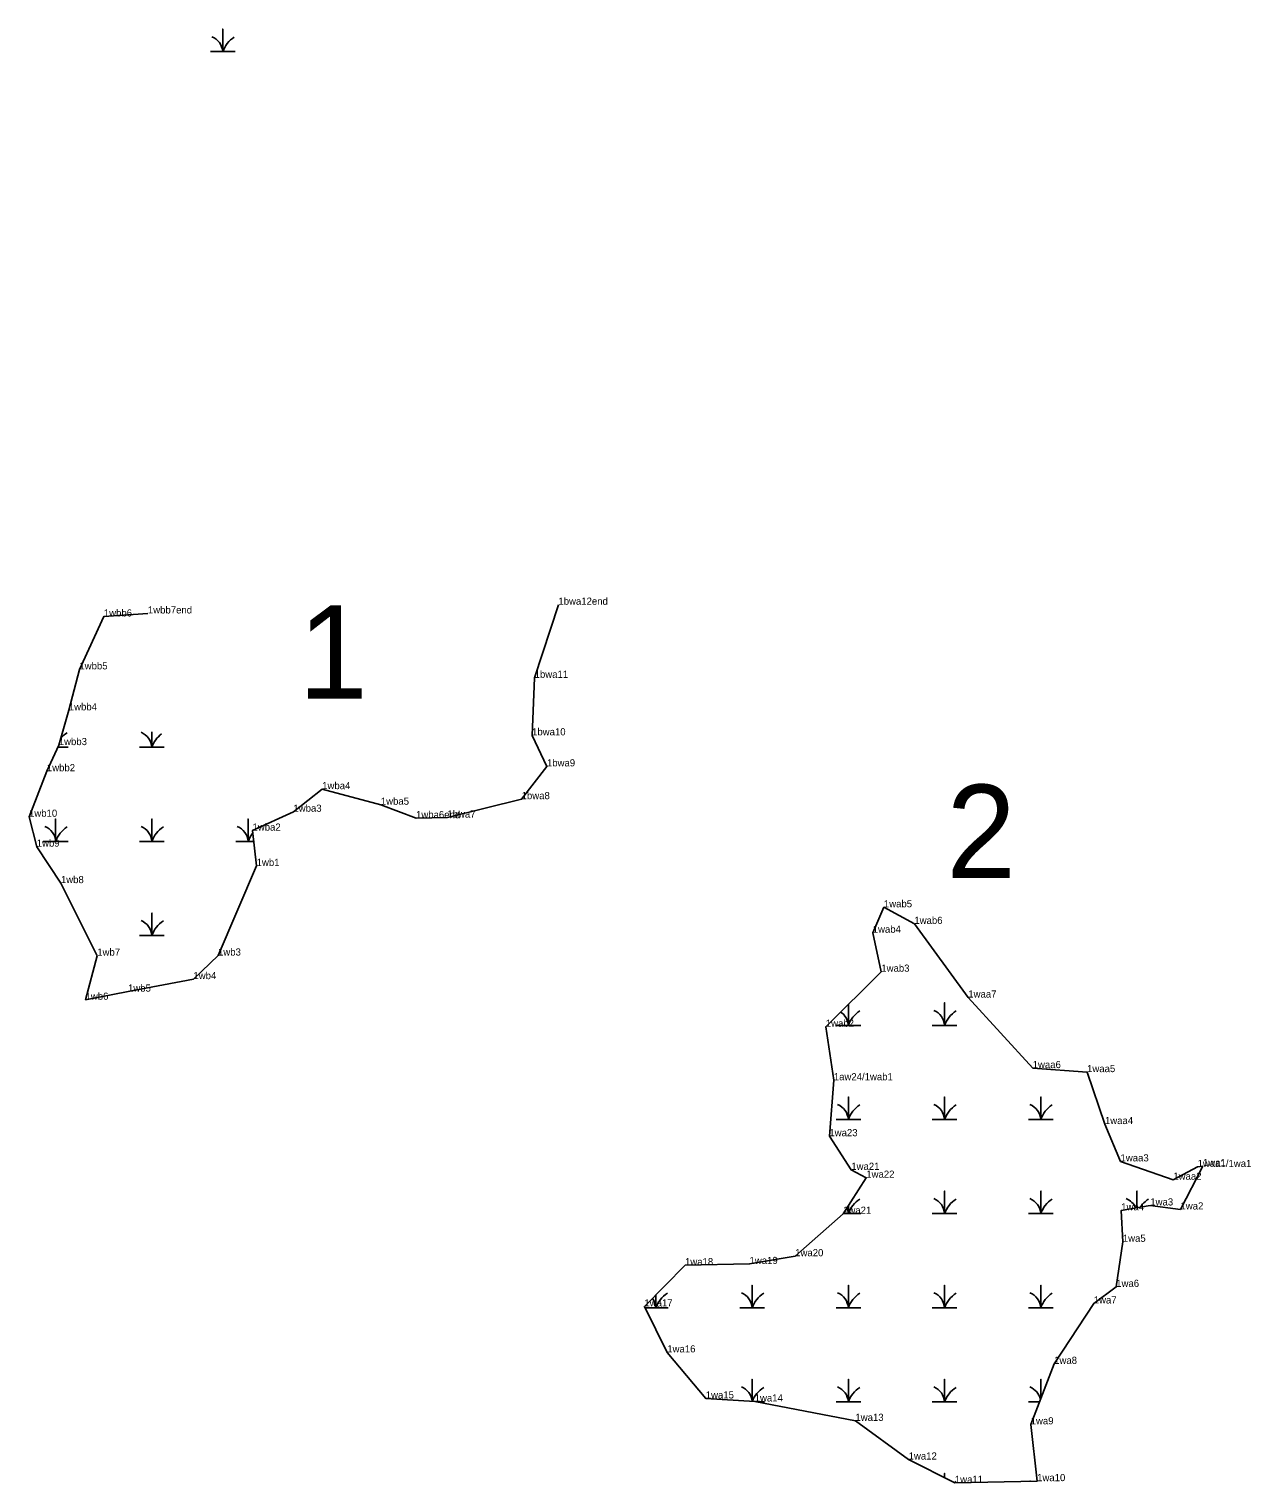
# Model space of a CAD drawing. Extents: x 2072529 to 2268796, y 436423 to 470406.
# Drawn here: x 2072529 to 2073383, y 469389 to 470406 of the extents above; entities that cross this region are included whole.
import ezdxf

# ---------------------------------------------------------------- set-up
doc = ezdxf.new("R2010")
doc.units = 0
for name, color, linetype in [('Default', 7, 'Continuous'), ('Exist Environmental Wetland Boundary', 7, 'Continuous'), ('Exist Environmental Wetland Boundary Cogo Comment', 7, 'Continuous'), ('Exist Hydro Swamp or Marsh', 7, 'Continuous'), ('Old_Level_20', 7, 'Continuous')]:
    doc.layers.add(name, color=color, linetype=linetype)

msp = doc.modelspace()

# ---------------------------------------------------------------- linework, layer by layer
at = {"layer": 'Exist Environmental Wetland Boundary'}
msp.add_line((2073333.7, 469580.5), (2073349.4, 469610.8), dxfattribs=at)
for points in [[(2072612, 469997.1), (2072581.2, 469995), (2072564.1, 469958), (2072556.7, 469929.4), (2072549.7, 469905.1), (2072541.4, 469886.8), (2072528.9, 469855)], [(2072898.9, 470003.2), (2072882.3, 469952.1), (2072880.5, 469911.9), (2072890.9, 469890.2), (2072873.2, 469867.3), (2072821.3, 469854.4), (2072799.4, 469854)], [(2072799.4, 469854), (2072774.8, 469863.4), (2072733.8, 469874.3), (2072713.7, 469858.5), (2072685.1, 469845.3), (2072688, 469820.6)], [(2072528.9, 469855), (2072534.3, 469834.1), (2072551.2, 469808.6), (2072576.6, 469757.9), (2072568.4, 469727.1), (2072598.1, 469732.8), (2072643.8, 469741.5), (2072661, 469758), (2072688, 469820.6)], [(2073091.4, 469670.8), (2073085.8, 469708.2), (2073124.6, 469746.7), (2073118.6, 469773.9), (2073126.4, 469791.7), (2073147.7, 469780.1), (2073185.4, 469728.6), (2073230.4, 469679.3), (2073268.4, 469676.5), (2073280.9, 469640.2), (2073291.8, 469614.1), (2073328.7, 469601.3), (2073345.7, 469610.2), (2073349.4, 469610.8)], [(2073091.4, 469670.8), (2073088.3, 469631.7), (2073103.6, 469608.2), (2073114.1, 469602.7), (2073097.9, 469577.5), (2073064.4, 469547.8), (2073032.5, 469542.4), (2072987.4, 469541.5), (2072959, 469512.7), (2072975, 469480.6), (2073001.9, 469448.4), (2073036.1, 469446.3), (2073106.5, 469432.7), (2073143.7, 469405.7), (2073176, 469389.4), (2073233.5, 469390.6), (2073229, 469430.3), (2073245.4, 469472.6), (2073273.1, 469514.8), (2073288.8, 469526.4), (2073293.4, 469557.9), (2073292.3, 469579.9), (2073312.6, 469583.3), (2073333.7, 469580.5)]]:
    msp.add_lwpolyline(points, dxfattribs=at)
at = {"layer": 'Exist Hydro Swamp or Marsh'}
msp.add_line((2072664.3, 470396.9), (2072664.3, 470396.9), dxfattribs=at)
for points in [[(2072655.7, 470389.8), (2072664.3, 470389.8), (2072664.3, 470405.6), (2072664.3, 470389.8), (2072672.9, 470389.8)], [(2072606.2, 469903.6), (2072614.8, 469903.6), (2072614.8, 469914.4)], [(2072614.8, 469914.4), (2072614.8, 469903.6), (2072623.4, 469903.6)], [(2072549, 469903.6), (2072556.2, 469903.6)], [(2072538.9, 469837.8), (2072547.5, 469837.8), (2072547.5, 469853.5), (2072547.5, 469837.8), (2072556.2, 469837.8)], [(2072606.2, 469837.8), (2072614.8, 469837.8), (2072614.8, 469853.5), (2072614.8, 469837.8), (2072623.4, 469837.8)], [(2072673.4, 469837.8), (2072682, 469837.8), (2072682, 469853.5), (2072682, 469837.8), (2072686, 469837.8)], [(2072606.2, 469772), (2072614.8, 469772), (2072614.8, 469787.7), (2072614.8, 469772), (2072623.4, 469772)], [(2073093, 469709.2), (2073101.6, 469709.2), (2073101.6, 469723.9)], [(2073101.6, 469723.9), (2073101.6, 469709.2), (2073110.2, 469709.2)], [(2073160.2, 469709.2), (2073168.8, 469709.2), (2073168.8, 469725), (2073168.8, 469709.2), (2073177.4, 469709.2)], [(2073093, 469643.4), (2073101.6, 469643.4), (2073101.6, 469659.2), (2073101.6, 469643.4), (2073110.2, 469643.4)], [(2073160.2, 469643.4), (2073168.8, 469643.4), (2073168.8, 469659.2), (2073168.8, 469643.4), (2073177.4, 469643.4)], [(2073227.5, 469643.4), (2073236.1, 469643.4), (2073236.1, 469659.2), (2073236.1, 469643.4), (2073244.7, 469643.4)], [(2073160.2, 469577.6), (2073168.8, 469577.6), (2073168.8, 469593.4), (2073168.8, 469577.6), (2073177.4, 469577.6)], [(2073227.5, 469577.6), (2073236.1, 469577.6), (2073236.1, 469593.4), (2073236.1, 469577.6), (2073244.7, 469577.6)], [(2073303.3, 469581.7), (2073303.3, 469593.4), (2073303.3, 469581.7)], [(2073098, 469577.6), (2073101.6, 469577.6), (2073101.6, 469583.2)], [(2073101.6, 469583.2), (2073101.6, 469577.6), (2073110.2, 469577.6)], [(2072959.5, 469511.8), (2072967.1, 469511.8), (2072967.1, 469520.9)], [(2072967.1, 469520.9), (2072967.1, 469511.8), (2072975.7, 469511.8)], [(2073025.7, 469511.8), (2073034.3, 469511.8), (2073034.3, 469527.6), (2073034.3, 469511.8), (2073042.9, 469511.8)], [(2073093, 469511.8), (2073101.6, 469511.8), (2073101.6, 469527.6), (2073101.6, 469511.8), (2073110.2, 469511.8)], [(2073160.2, 469511.8), (2073168.8, 469511.8), (2073168.8, 469527.6), (2073168.8, 469511.8), (2073177.4, 469511.8)], [(2073227.5, 469511.8), (2073236.1, 469511.8), (2073236.1, 469527.6), (2073236.1, 469511.8), (2073244.7, 469511.8)], [(2073034.3, 469446.4), (2073034.3, 469461.8), (2073034.3, 469446.4)], [(2073093, 469446), (2073101.6, 469446), (2073101.6, 469461.8), (2073101.6, 469446), (2073110.2, 469446)], [(2073160.2, 469446), (2073168.8, 469446), (2073168.8, 469461.8), (2073168.8, 469446), (2073177.4, 469446)], [(2073236.1, 469448.5), (2073236.1, 469461.8), (2073236.1, 469448.5)], [(2073037.7, 469446), (2073042.9, 469446)], [(2073227.5, 469446), (2073235.1, 469446)], [(2073168.8, 469393), (2073168.8, 469396), (2073168.8, 469393)]]:
    msp.add_lwpolyline(points, dxfattribs=at)
for centre, radius, start, end in [((2072652, 470388.9), 12.3, 4.1403, 67.535), ((2072682.6, 470383.7), 19.2, 122.1274, 161.6222), ((2072565.8, 469897.5), 19.2, 122.1274, 139.9617), ((2072602.5, 469902.7), 12.3, 4.1403, 67.535), ((2072633, 469897.5), 19.2, 126.6727, 161.6222), ((2072535.3, 469836.9), 12.3, 4.1403, 67.535), ((2072565.8, 469831.7), 19.2, 122.1274, 161.6222), ((2072602.5, 469836.9), 12.3, 4.1403, 67.535), ((2072633, 469831.7), 19.2, 122.1274, 161.6222), ((2072669.8, 469836.9), 12.3, 4.1403, 67.535), ((2072700.3, 469831.7), 19.2, 122.1274, 127.5328), ((2072700.3, 469831.7), 19.2, 141.3706, 161.6222), ((2072602.5, 469771.1), 12.3, 4.1403, 67.535), ((2072633, 469765.9), 19.2, 122.1274, 161.6222), ((2073089.3, 469708.3), 12.3, 4.1403, 56.041), ((2073119.8, 469703.1), 19.2, 122.1274, 161.6222), ((2073156.6, 469708.3), 12.3, 4.1403, 67.535), ((2073187.1, 469703.1), 19.2, 122.1274, 161.6222), ((2073089.3, 469642.5), 12.3, 4.1403, 67.535), ((2073119.8, 469637.3), 19.2, 122.1274, 161.6222), ((2073156.6, 469642.5), 12.3, 4.1403, 67.535), ((2073187.1, 469637.3), 19.2, 122.1274, 161.6222), ((2073223.8, 469642.5), 12.3, 4.1403, 67.535), ((2073254.3, 469637.3), 19.2, 122.1274, 161.6222), ((2073089.3, 469576.7), 12.3, 4.1403, 23.6306), ((2073119.8, 469571.5), 19.2, 122.1274, 161.6222), ((2073156.6, 469576.7), 12.3, 4.1403, 67.535), ((2073187.1, 469571.5), 19.2, 122.1274, 161.6222), ((2073223.8, 469576.7), 12.3, 4.1403, 67.535), ((2073254.3, 469571.5), 19.2, 122.1274, 161.6222), ((2073291.1, 469576.7), 12.3, 23.2398, 67.535), ((2073321.6, 469571.5), 19.2, 122.1274, 146.73), ((2072985.3, 469505.7), 19.2, 122.1274, 161.6222), ((2073022.1, 469510.9), 12.3, 4.1403, 67.535), ((2073052.6, 469505.7), 19.2, 122.1274, 161.6222), ((2073089.3, 469510.9), 12.3, 4.1403, 67.535), ((2073119.8, 469505.7), 19.2, 122.1274, 161.6222), ((2073156.6, 469510.9), 12.3, 4.1403, 67.535), ((2073187.1, 469505.7), 19.2, 122.1274, 161.6222), ((2073223.8, 469510.9), 12.3, 4.1403, 67.535), ((2073254.3, 469505.7), 19.2, 122.1274, 161.6222), ((2072954.8, 469510.9), 12.3, 4.1403, 37.2107), ((2073022.1, 469445.1), 12.3, 6.1296, 67.535), ((2073052.6, 469439.9), 19.2, 122.1274, 160.3165), ((2073089.3, 469445.1), 12.3, 4.1403, 67.535), ((2073119.8, 469439.9), 19.2, 122.1274, 161.6222), ((2073156.6, 469445.1), 12.3, 4.1403, 67.535), ((2073187.1, 469439.9), 19.2, 122.1274, 161.6222), ((2073223.8, 469445.1), 12.3, 12.7529, 67.535), ((2073187.1, 469374.1), 19.2, 122.1274, 126.467), ((2073223.8, 469379.3), 12.3, 65.6117, 67.535)]:
    msp.add_arc(centre, radius, start, end, dxfattribs=at)
at = {"layer": 'Old_Level_20'}
for p, q in [((2072612, 469997.1), (2072612, 469997.1)), ((2072898.8, 470003.3), (2072898.8, 470003.3)), ((2072581.2, 469995), (2072581.2, 469995)), ((2072564.1, 469958), (2072564.1, 469958)), ((2072882.3, 469952.1), (2072882.3, 469952.1)), ((2072556.7, 469929.4), (2072556.7, 469929.4)), ((2072549.7, 469905.1), (2072549.7, 469905.1)), ((2072880.5, 469911.9), (2072880.5, 469911.9)), ((2072541.4, 469886.8), (2072541.4, 469886.8)), ((2072890.9, 469890.2), (2072890.9, 469890.2)), ((2072733.8, 469874.3), (2072733.8, 469874.3)), ((2072873.2, 469867.3), (2072873.2, 469867.3)), ((2072528.9, 469855), (2072528.9, 469855)), ((2072713.7, 469858.5), (2072713.7, 469858.5)), ((2072774.8, 469863.4), (2072774.8, 469863.4)), ((2072821.3, 469854.4), (2072821.3, 469854.4)), ((2072685.1, 469845.3), (2072685.1, 469845.3)), ((2072799.4, 469854), (2072799.4, 469854)), ((2072534.3, 469834.1), (2072534.3, 469834.1)), ((2072688, 469820.6), (2072688, 469820.6)), ((2072551.2, 469808.6), (2072551.2, 469808.6)), ((2073126.4, 469791.7), (2073126.4, 469791.7)), ((2073118.6, 469773.9), (2073118.6, 469773.9)), ((2073118.6, 469773.9), (2073118.6, 469773.9)), ((2073118.6, 469773.9), (2073118.6, 469773.9)), ((2073147.7, 469780.1), (2073147.7, 469780.1)), ((2073147.7, 469780.1), (2073147.7, 469780.1)), ((2073147.7, 469780.1), (2073147.7, 469780.1)), ((2072576.6, 469757.9), (2072576.6, 469757.9)), ((2072661, 469758), (2072661, 469758)), ((2073124.6, 469746.7), (2073124.6, 469746.7)), ((2072598.1, 469732.8), (2072598.1, 469732.8)), ((2072643.8, 469741.5), (2072643.8, 469741.5)), ((2072568.4, 469727.1), (2072568.4, 469727.1)), ((2073185.4, 469728.6), (2073185.4, 469728.6)), ((2073185.4, 469728.6), (2073185.4, 469728.6)), ((2073185.4, 469728.6), (2073185.4, 469728.6)), ((2073085.8, 469708.2), (2073085.8, 469708.2)), ((2073085.8, 469708.2), (2073085.8, 469708.2)), ((2073085.8, 469708.2), (2073085.8, 469708.2)), ((2073230.4, 469679.3), (2073230.4, 469679.3)), ((2073268.4, 469676.5), (2073268.4, 469676.5)), ((2073268.4, 469676.5), (2073268.4, 469676.5)), ((2073268.4, 469676.5), (2073268.4, 469676.5)), ((2073091.4, 469670.8), (2073091.4, 469670.8)), ((2073088.3, 469631.7), (2073088.3, 469631.7)), ((2073280.9, 469640.2), (2073280.9, 469640.2)), ((2073291.8, 469614.1), (2073291.8, 469614.1)), ((2073291.8, 469614.1), (2073291.8, 469614.1)), ((2073291.8, 469614.1), (2073291.8, 469614.1)), ((2073345.7, 469610.2), (2073345.7, 469610.2)), ((2073349.4, 469610.8), (2073349.4, 469610.8)), ((2073103.6, 469608.2), (2073103.6, 469608.2)), ((2073114.1, 469602.7), (2073114.1, 469602.7)), ((2073328.7, 469601.3), (2073328.7, 469601.3)), ((2073292.3, 469579.9), (2073292.3, 469579.9)), ((2073312.6, 469583.3), (2073312.6, 469583.3)), ((2073333.7, 469580.5), (2073333.7, 469580.5)), ((2073097.9, 469577.5), (2073097.9, 469577.5)), ((2073293.4, 469557.9), (2073293.4, 469557.9)), ((2072987.4, 469541.5), (2072987.4, 469541.5)), ((2073032.5, 469542.4), (2073032.5, 469542.4)), ((2073064.4, 469547.8), (2073064.4, 469547.8)), ((2073288.8, 469526.4), (2073288.8, 469526.4)), ((2072959, 469512.7), (2072959, 469512.7)), ((2073273.1, 469514.8), (2073273.1, 469514.8)), ((2072975, 469480.6), (2072975, 469480.6)), ((2073245.4, 469472.6), (2073245.4, 469472.6)), ((2073001.9, 469448.4), (2073001.9, 469448.4)), ((2073036.1, 469446.3), (2073036.1, 469446.3)), ((2073106.5, 469432.7), (2073106.5, 469432.7)), ((2073229, 469430.3), (2073229, 469430.3)), ((2073143.7, 469405.7), (2073143.7, 469405.7)), ((2073176, 469389.4), (2073176, 469389.4)), ((2073233.5, 469390.6), (2073233.5, 469390.6))]:
    msp.add_line(p, q, dxfattribs=at)

# ---------------------------------------------------------------- texts
at = {"layer": 'Default'}
for s, p in [('1', (2072717.2, 469937.6)), ('2', (2073170.1, 469812.1))]:
    msp.add_text(s, height=65.3, dxfattribs=at).set_placement(p)
at = {"layer": 'Exist Environmental Wetland Boundary Cogo Comment'}
for s, p in [('1bwa12end', (2072898.9, 470003.2)), ('1wbb6', (2072581.2, 469995)), ('1wbb7end', (2072612, 469997.1)), ('1wbb5', (2072564.1, 469958)), ('1bwa11', (2072882.3, 469952.1)), ('1wbb4', (2072556.7, 469929.4)), ('1bwa10', (2072880.5, 469911.9)), ('1wbb3', (2072549.7, 469905.1)), ('1bwa9', (2072890.9, 469890.2)), ('1wbb2', (2072541.4, 469886.8)), ('1wba4', (2072733.8, 469874.3)), ('1wba5', (2072774.8, 469863.4)), ('1bwa8', (2072873.2, 469867.3)), ('1wb10', (2072528.9, 469855)), ('1wba3', (2072713.7, 469858.5)), ('1wba6end', (2072799.4, 469854)), ('1bwa7', (2072821.3, 469854.4)), ('1wba2', (2072685.1, 469845.3)), ('1wb9', (2072534.3, 469834.1)), ('1wb1', (2072688, 469820.6)), ('1wb8', (2072551.2, 469808.6)), ('1wab5', (2073126.4, 469791.7)), ('1wab6', (2073147.7, 469780.1)), ('1wab4', (2073118.6, 469773.9)), ('1wb7', (2072576.6, 469757.9)), ('1wb3', (2072661, 469758)), ('1wb4', (2072643.8, 469741.5)), ('1wab3', (2073124.6, 469746.7)), ('1wb6', (2072568.4, 469727.1)), ('1wb5', (2072598.1, 469732.8)), ('1waa7', (2073185.4, 469728.6)), ('1wab2', (2073085.8, 469708.2)), ('1waa6', (2073230.4, 469679.3)), ('1waa5', (2073268.4, 469676.5)), ('1aw24/1wab1', (2073091.4, 469670.8)), ('1aw24', (2073091.4, 469670.8)), ('1waa4', (2073280.9, 469640.2)), ('1wa23', (2073088.3, 469631.7)), ('1wa21', (2073103.6, 469608.2)), ('1waa3', (2073291.8, 469614.1)), ('1waa1/1wa1', (2073345.7, 469610.2)), ('1wa1', (2073349.4, 469610.8)), ('1wa22', (2073114.1, 469602.7)), ('1waa2', (2073328.7, 469601.3)), ('1wa21', (2073097.9, 469577.5)), ('1wa4', (2073292.3, 469579.9)), ('1wa3', (2073312.6, 469583.3)), ('1wa2', (2073333.7, 469580.5)), ('1wa5', (2073293.4, 469557.9)), ('1wa20', (2073064.4, 469547.8)), ('1wa18', (2072987.4, 469541.5)), ('1wa19', (2073032.5, 469542.4)), ('1wa6', (2073288.8, 469526.4)), ('1wa7', (2073273.1, 469514.8)), ('1wa17', (2072959, 469512.7)), ('1wa16', (2072975, 469480.6)), ('1wa8', (2073245.4, 469472.6)), ('1wa15', (2073001.9, 469448.4)), ('1wa14', (2073036.1, 469446.3)), ('1wa13', (2073106.5, 469432.7)), ('1wa9', (2073229, 469430.3)), ('1wa12', (2073143.7, 469405.7)), ('1wa11', (2073176, 469389.4)), ('1wa10', (2073233.5, 469390.6))]:
    msp.add_text(s, height=5, dxfattribs=at).set_placement(p)

doc.saveas('drawing.dxf')
